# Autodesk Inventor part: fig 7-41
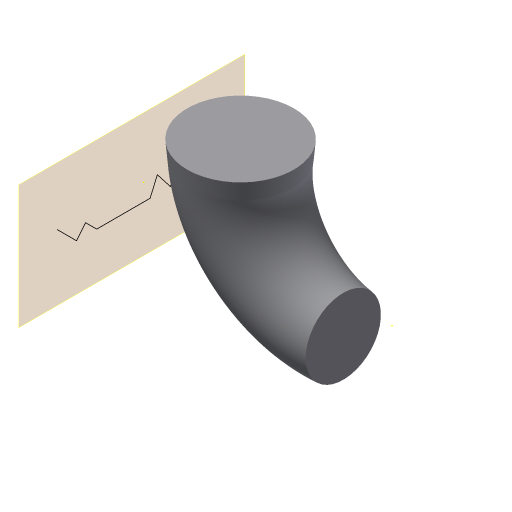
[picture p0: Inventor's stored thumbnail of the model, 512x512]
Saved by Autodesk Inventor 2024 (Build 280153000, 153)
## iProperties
Created: 2011-07
Part Number: fig 7-41
Material: Generic
Document SubType Name: Modeling
Designer: CadCim
Density: 1 g/cm^3
Appearance: Default
Author: CadCim
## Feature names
1. Sweep1
## Parameters: d0 = 5 deg, d1 = -14.75 mm, d2 = 0
